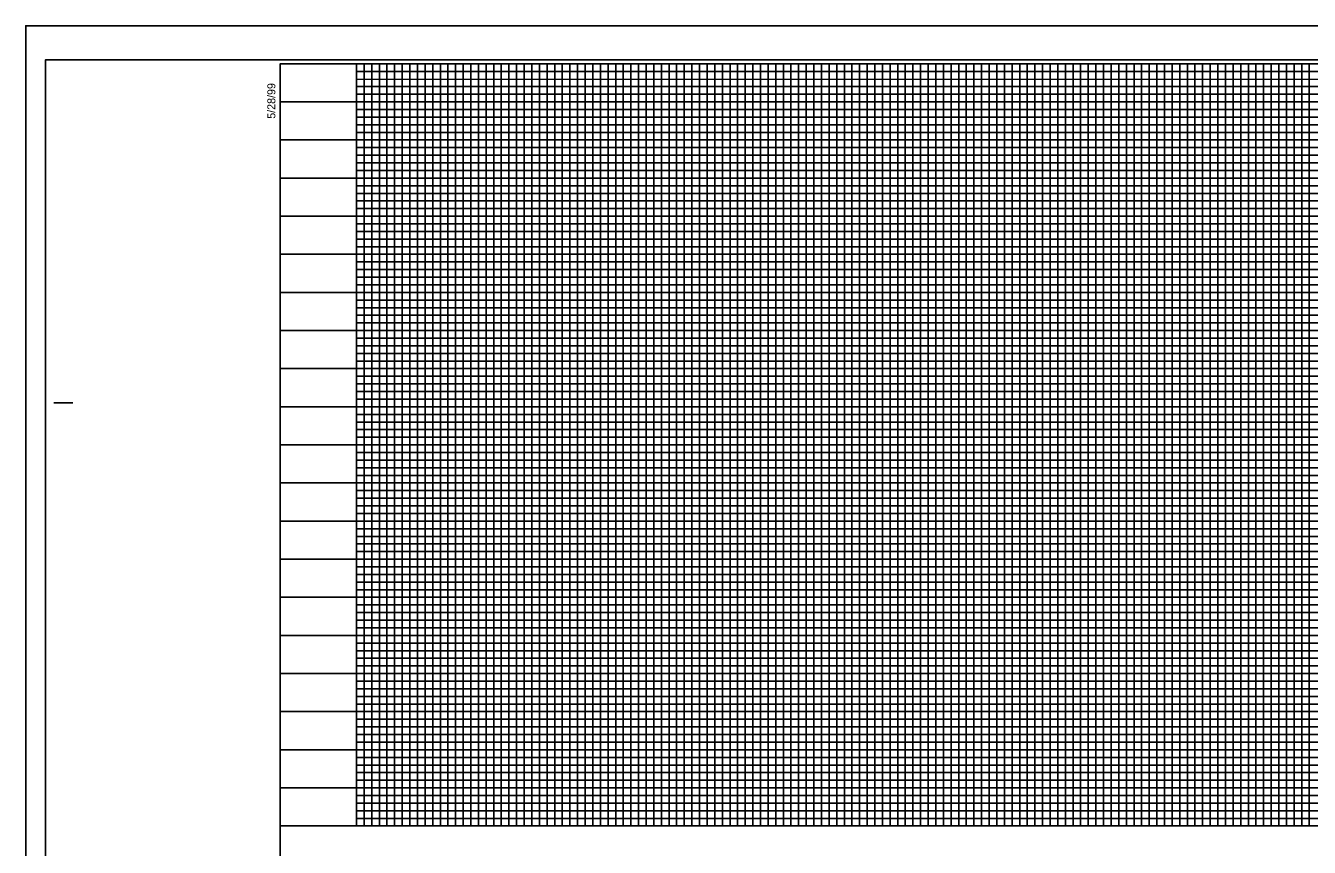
# Model space of a CAD drawing. Extents: x 2331575 to 2333259, y 609001 to 610101.
# Drawn here: x 2331575 to 2332417, y 609562 to 610101 of the extents above; entities that cross this region are included whole.
import ezdxf

# ---------------------------------------------------------------- set-up
doc = ezdxf.new("R2010")
doc.units = 0
for name, color, linetype in [('Sheet Cutting Line CELL', 7, 'Continuous'), ('Sheet DOT Grid CELL', 7, 'Continuous'), ('Sheet Layout Profile Border Port 1', 7, 'Continuous'), ('Sheet Plot Border Inside CELL', 7, 'Continuous'), ('Sheet Plot Border Outside CELL', 7, 'Continuous'), ('Sheet Profile CELL', 7, 'Continuous'), ('Sheet Profile Grid Major CELL', 7, 'Continuous'), ('Sheet Profile Grid Middle CELL', 7, 'Continuous'), ('Sheet Profile Grid Minor CELL', 7, 'Continuous')]:
    doc.layers.add(name, color=color, linetype=linetype)

msp = doc.modelspace()

# ---------------------------------------------------------------- linework, layer by layer
at = {"layer": 'Sheet Cutting Line CELL'}
for p, q in [((2333259.23, 610101.48), (2331575.23, 610101.48)), ((2331575.23, 610101.48), (2331575.23, 609001.48))]:
    msp.add_line(p, q, dxfattribs=at)
at = {"layer": 'Sheet DOT Grid CELL'}
for p, q in [((2331792.23, 609576.48), (2331792.23, 610076.48)), ((2331842.23, 609576.48), (2331842.23, 610076.48)), ((2331892.23, 609576.48), (2331892.23, 610076.48)), ((2331942.23, 609576.48), (2331942.23, 610076.48)), ((2331992.23, 609576.48), (2331992.23, 610076.48)), ((2332042.23, 609576.48), (2332042.23, 610076.48)), ((2332092.23, 609576.48), (2332092.23, 610076.48)), ((2332142.23, 609576.48), (2332142.23, 610076.48)), ((2332192.23, 609576.48), (2332192.23, 610076.48)), ((2332242.23, 609576.48), (2332242.23, 610076.48)), ((2332292.23, 609576.48), (2332292.23, 610076.48)), ((2332342.23, 609576.48), (2332342.23, 610076.48)), ((2332392.23, 609576.48), (2332392.23, 610076.48)), ((2333042.18, 610026.48), (2331742.23, 610026.48)), ((2333042.18, 609976.48), (2331742.23, 609976.48)), ((2333042.23, 609926.48), (2331742.23, 609926.48)), ((2333242.23, 609876.48), (2331742.23, 609876.48)), ((2333242.23, 609826.48), (2331742.23, 609826.48)), ((2333242.23, 609776.48), (2331742.23, 609776.48)), ((2333242.23, 609726.48), (2331742.23, 609726.48)), ((2333242.23, 609676.48), (2331742.23, 609676.48)), ((2333242.23, 609626.48), (2331742.23, 609626.48))]:
    msp.add_line(p, q, dxfattribs=at)
at = {"layer": 'Sheet Layout Profile Border Port 1'}
msp.add_lwpolyline([(2331792.23, 609915.43), (2331792.23, 609576.48), (2333192.23, 609576.48), (2333192.23, 609915.43)], dxfattribs=at)
at = {"layer": 'Sheet Plot Border Inside CELL'}
msp.add_lwpolyline([(2331588.23, 609023.93), (2333254.73, 609023.93), (2333254.73, 610079.03), (2331588.23, 610079.03)], close=True, dxfattribs=at)
at = {"layer": 'Sheet Plot Border Outside CELL'}
msp.add_lwpolyline([(2331575.23, 609001.48), (2333259.23, 609001.48), (2333259.23, 610101.48), (2331575.23, 610101.48)], close=True, dxfattribs=at)
at = {"layer": 'Sheet Profile CELL'}
for p, q in [((2331593.73, 609853.98), (2331606.23, 609853.98)), ((2331742.23, 609576.48), (2333242.23, 609576.48))]:
    msp.add_line(p, q, dxfattribs=at)
msp.add_lwpolyline([(2333242.23, 610076.48), (2331742.23, 610076.48), (2331742.23, 609026.48), (2333242.23, 609026.48)], close=True, dxfattribs=at)
at = {"layer": 'Sheet Profile Grid Major CELL'}
for points in [[(2331792.23, 610076.48), (2331792.23, 609576.48), (2331842.23, 609576.48), (2331842.23, 610076.48), (2331892.23, 610076.48), (2331892.23, 609576.48), (2331942.23, 609576.48), (2331942.23, 610076.48), (2331992.23, 610076.48), (2331992.23, 609576.48), (2332042.23, 609576.48), (2332042.23, 610076.48), (2332092.23, 610076.48), (2332092.23, 609576.48), (2332142.23, 609576.48), (2332142.23, 610076.48), (2332192.23, 610076.48), (2332192.23, 609576.48), (2332242.23, 609576.48), (2332242.23, 610076.48), (2332292.23, 610076.48), (2332292.23, 609576.48), (2332342.23, 609576.48), (2332342.23, 610076.48), (2332392.23, 610076.48), (2332392.23, 609576.48), (2332442.23, 609576.48)], [(2331742.23, 610026.48), (2333042.23, 610026.48)], [(2333042.23, 609976.48), (2331742.23, 609976.48), (2331742.23, 609926.48), (2333042.23, 609926.48)], [(2333242.23, 609876.48), (2331742.23, 609876.48), (2331742.23, 609826.48), (2333242.23, 609826.48)], [(2333242.23, 609776.48), (2331742.23, 609776.48), (2331742.23, 609726.48), (2333242.23, 609726.48)], [(2333242.23, 609676.48), (2331742.23, 609676.48), (2331742.23, 609676.48), (2331742.23, 609626.48), (2333242.23, 609626.48)]]:
    msp.add_lwpolyline(points, dxfattribs=at)
at = {"layer": 'Sheet Profile Grid Middle CELL'}
msp.add_line((2331742.23, 610051.48), (2333042.18, 610051.48), dxfattribs=at)
for points in [[(2331817.23, 610076.48), (2331817.23, 609576.48), (2331867.23, 609576.48), (2331867.23, 610076.48), (2331917.23, 610076.48), (2331917.23, 609576.48), (2331967.23, 609576.48), (2331967.23, 610076.48), (2332017.23, 610076.48), (2332017.23, 609576.48), (2332067.23, 609576.48), (2332067.23, 610076.48), (2332117.23, 610076.48), (2332117.23, 609576.48), (2332167.23, 609576.48), (2332167.23, 610076.48), (2332217.23, 610076.48), (2332217.23, 609576.48), (2332267.23, 609576.48), (2332267.23, 610076.48), (2332317.23, 610076.48), (2332317.23, 609576.48), (2332367.23, 609576.48), (2332367.23, 609576.48), (2332367.23, 610076.48), (2332417.23, 610076.48), (2332417.23, 609576.48), (2332467.23, 609576.48)], [(2333042.23, 610001.48), (2331742.23, 610001.48), (2331742.23, 609951.48), (2333042.23, 609951.48)], [(2333242.23, 609901.48), (2331742.23, 609901.48), (2331742.23, 609851.48), (2333067.23, 609851.48)], [(2333242.23, 609801.48), (2331742.23, 609801.48), (2331742.23, 609751.48), (2333242.23, 609751.48)], [(2333242.23, 609701.48), (2331742.23, 609701.48), (2331742.23, 609651.48), (2333242.23, 609651.48)], [(2333242.23, 609601.48), (2331742.23, 609601.48)]]:
    msp.add_lwpolyline(points, dxfattribs=at)
at = {"layer": 'Sheet Profile Grid Minor CELL'}
for p, q in [((2331792.23, 610071.48), (2333042.23, 610071.48)), ((2331792.23, 610066.48), (2331792.23, 610066.48)), ((2333042.23, 610066.48), (2331792.23, 610066.13)), ((2331792.23, 610061.48), (2333042.23, 610061.48)), ((2333042.18, 609941.48), (2331792.23, 609941.48)), ((2333042.23, 609936.48), (2331792.23, 609936.48)), ((2333042.23, 609931.48), (2331792.23, 609931.48)), ((2331792.23, 609921.48), (2333042.23, 609921.48)), ((2333042.23, 609916.48), (2331792.23, 609916.48)), ((2331792.23, 609911.48), (2333192.23, 609911.48)), ((2333192.23, 609891.48), (2331792.23, 609891.48)), ((2331792.23, 609886.48), (2333192.23, 609886.48)), ((2333192.23, 609866.48), (2331792.23, 609866.48)), ((2331792.23, 609861.48), (2333192.23, 609861.48)), ((2333192.23, 609841.48), (2331792.23, 609841.48)), ((2331792.23, 609836.48), (2333192.23, 609836.48)), ((2333192.23, 609831.48), (2331792.23, 609831.48)), ((2331792.23, 609821.48), (2333192.23, 609821.48)), ((2333192.23, 609816.48), (2331792.23, 609816.48)), ((2331792.23, 609811.48), (2333192.23, 609811.48)), ((2333192.23, 609806.48), (2331792.23, 609806.48)), ((2331792.23, 609796.48), (2333192.23, 609796.48)), ((2333192.23, 609791.48), (2331792.23, 609791.48)), ((2331792.23, 609786.48), (2333192.23, 609786.48)), ((2333192.23, 609781.48), (2331792.23, 609781.48)), ((2331792.23, 609771.48), (2333192.23, 609771.48)), ((2333192.23, 609766.48), (2331792.23, 609766.48)), ((2331792.23, 609761.48), (2333192.23, 609761.48)), ((2333192.23, 609756.48), (2331792.23, 609756.48)), ((2331792.23, 609746.48), (2333192.23, 609746.48)), ((2333192.23, 609741.48), (2331792.23, 609741.48)), ((2331792.23, 609736.48), (2333192.23, 609736.48)), ((2333192.23, 609731.48), (2331792.23, 609731.48)), ((2331792.23, 609721.48), (2333192.23, 609721.48)), ((2333192.23, 609716.48), (2331792.23, 609716.48)), ((2331792.23, 609711.48), (2333192.23, 609711.48)), ((2333192.23, 609706.48), (2331792.23, 609706.48)), ((2331792.23, 609696.48), (2333192.23, 609696.48)), ((2333192.23, 609691.48), (2331792.23, 609691.48)), ((2333192.23, 609686.48), (2331792.23, 609686.48)), ((2333192.23, 609681.48), (2331792.23, 609681.48)), ((2331792.23, 609671.48), (2333192.23, 609671.48)), ((2333192.23, 609666.48), (2331792.23, 609666.48)), ((2331792.23, 609661.48), (2333192.23, 609661.48)), ((2333192.23, 609656.48), (2331792.23, 609656.48)), ((2331792.23, 609646.48), (2333192.23, 609646.48)), ((2333192.23, 609641.48), (2331792.23, 609641.48)), ((2331792.23, 609636.48), (2333192.23, 609636.48)), ((2333192.23, 609631.48), (2331792.23, 609631.48)), ((2331792.23, 609621.48), (2333192.23, 609621.48)), ((2333192.23, 609616.48), (2331792.23, 609616.48)), ((2331792.23, 609611.48), (2333192.23, 609611.48)), ((2333192.23, 609606.48), (2331792.23, 609606.48)), ((2331792.23, 609596.48), (2333192.23, 609596.48)), ((2333192.23, 609591.48), (2331792.23, 609591.48)), ((2331792.23, 609586.48), (2333192.23, 609586.48))]:
    msp.add_line(p, q, dxfattribs=at)
for points in [[(2331797.23, 610076.48), (2331797.23, 609576.48), (2331802.23, 609576.48), (2331802.23, 610076.48), (2331807.23, 610076.48), (2331807.23, 609576.48), (2331812.23, 609576.48), (2331812.23, 610076.48), (2331822.23, 610076.48), (2331822.23, 609576.48), (2331827.23, 609576.48), (2331827.23, 610076.48), (2331832.23, 610076.48), (2331832.23, 609576.48), (2331837.23, 609576.48), (2331847.23, 609576.48), (2331852.23, 609576.48), (2331852.23, 610076.48), (2331857.23, 610076.48), (2331857.23, 609576.48), (2331862.23, 609576.48), (2331862.23, 610076.48), (2331872.23, 610076.48), (2331872.23, 609576.48), (2331877.23, 609576.48), (2331877.23, 610076.48), (2331882.23, 610076.48), (2331882.23, 609576.48), (2331887.23, 609576.48), (2331887.23, 610076.48), (2331897.23, 610076.48), (2331897.23, 609576.48), (2331902.23, 609576.48), (2331902.23, 610076.48), (2331907.23, 610076.48), (2331907.23, 609576.48), (2331912.23, 609576.48), (2331912.23, 610076.48), (2331922.23, 610076.48), (2331922.23, 609576.48), (2331927.23, 609576.48), (2331927.23, 610076.48), (2331932.23, 610076.48), (2331932.23, 609576.48), (2331937.23, 609576.48), (2331937.23, 610076.48), (2331947.23, 610076.48), (2331947.23, 609576.48), (2331952.23, 609576.48), (2331952.23, 610076.48), (2331957.23, 610076.48), (2331957.23, 609576.48), (2331962.23, 609576.48), (2331962.23, 610076.48), (2331972.23, 610076.48), (2331972.23, 609576.48), (2331977.23, 609576.48), (2331977.23, 610076.48), (2331982.23, 610076.48), (2331982.23, 609576.48), (2331987.23, 609576.48), (2331987.23, 610076.48), (2331997.23, 610076.48), (2331997.23, 609576.48), (2332002.23, 609576.48), (2332002.23, 610076.48), (2332007.23, 610076.48), (2332007.23, 609576.48)], [(2331837.23, 609576.48), (2331837.23, 610076.48), (2331847.23, 610076.48), (2331847.23, 609576.48)], [(2332007.23, 609576.48), (2332012.23, 609576.48), (2332012.23, 610076.48), (2332022.23, 610076.48), (2332022.23, 609576.48), (2332027.23, 609576.48), (2332027.23, 610076.48), (2332032.23, 610076.48), (2332032.23, 609576.48), (2332037.23, 609576.48), (2332037.23, 610076.48), (2332047.23, 610076.48), (2332047.23, 609576.48), (2332052.23, 609576.48), (2332052.23, 610076.48), (2332057.23, 610076.48), (2332057.23, 609576.48), (2332062.23, 609576.48), (2332062.23, 610076.48), (2332072.23, 610076.48), (2332072.23, 609576.48), (2332077.23, 609576.48), (2332077.23, 610076.48), (2332082.23, 610076.48), (2332082.23, 609576.48), (2332087.23, 609576.48), (2332087.23, 610076.48), (2332097.23, 610076.48), (2332097.23, 609576.48), (2332102.23, 609576.48), (2332102.23, 610076.48), (2332107.23, 610076.48), (2332107.23, 609576.48), (2332112.23, 609576.48), (2332112.23, 610076.48), (2332122.23, 610076.48), (2332122.23, 609576.48), (2332127.23, 609576.48), (2332127.23, 610076.48), (2332132.23, 610076.48), (2332132.23, 609576.48), (2332137.23, 609576.48), (2332137.23, 610076.48), (2332147.23, 610076.48), (2332147.23, 609576.48), (2332152.23, 609576.48), (2332152.23, 610076.48), (2332157.23, 610076.48), (2332157.23, 609576.48), (2332162.23, 609576.48), (2332162.23, 610076.48), (2332172.23, 610076.48), (2332172.23, 609576.48), (2332177.23, 609576.48), (2332177.23, 610076.48), (2332182.23, 610076.48), (2332182.23, 609576.48), (2332187.23, 609576.48), (2332187.23, 610076.48), (2332197.23, 610076.48), (2332197.23, 609576.48), (2332202.23, 609576.48), (2332202.23, 610076.48), (2332207.23, 610076.48), (2332207.23, 609576.48), (2332212.23, 609576.48), (2332212.23, 610076.48), (2332222.23, 610076.48), (2332222.23, 609576.48), (2332227.23, 609576.48), (2332227.23, 610076.48), (2332232.23, 610076.48), (2332232.23, 609576.48), (2332237.23, 609576.48), (2332237.23, 610076.48), (2332247.23, 610076.48), (2332247.23, 609576.48), (2332252.23, 609576.48), (2332252.23, 610076.48), (2332257.23, 610076.48), (2332257.23, 609576.48), (2332262.23, 609576.48), (2332262.23, 610076.48), (2332272.23, 610076.48), (2332272.23, 609576.48), (2332277.23, 609576.48), (2332277.23, 610076.48), (2332282.23, 610076.48), (2332282.23, 609576.48), (2332287.23, 609576.48), (2332287.23, 610076.48), (2332297.23, 610076.48), (2332297.23, 609576.48), (2332302.23, 609576.48), (2332302.23, 610076.48), (2332307.23, 610076.48), (2332307.23, 609576.48), (2332312.23, 609576.48), (2332312.23, 610076.48), (2332322.23, 610076.48)], [(2332322.23, 610076.48), (2332322.23, 609576.48), (2332327.23, 609576.48), (2332327.23, 610076.48), (2332332.23, 610076.48), (2332332.23, 609576.48), (2332337.23, 609576.48), (2332337.23, 610076.48), (2332347.23, 610076.48), (2332347.23, 609576.48), (2332352.23, 609576.48), (2332352.23, 610076.48), (2332357.23, 610076.48), (2332357.23, 609576.48), (2332362.23, 609576.48), (2332362.23, 610076.48), (2332372.23, 610076.48), (2332372.23, 609576.48), (2332377.23, 609576.48), (2332377.23, 610076.48), (2332382.23, 610076.48), (2332382.23, 609576.48), (2332387.23, 609576.48), (2332387.23, 610076.48), (2332397.23, 610076.48), (2332397.23, 609576.48), (2332402.23, 609576.48), (2332402.23, 610076.48), (2332407.23, 610076.48), (2332407.23, 609576.48), (2332412.23, 609576.48), (2332412.23, 610076.48), (2332422.23, 610076.48)], [(2333042.23, 610056.48), (2331792.23, 610056.48), (2331792.23, 610046.48), (2333042.23, 610046.48)], [(2333042.18, 610041.48), (2331792.23, 610041.48), (2331792.23, 610036.48), (2333042.23, 610036.48)], [(2333042.23, 610031.48), (2331792.23, 610031.48), (2331792.23, 610021.48), (2333042.23, 610021.48)], [(2333042.23, 610016.48), (2331792.23, 610016.48), (2331792.23, 610011.48), (2333042.23, 610011.48)], [(2333042.23, 610006.48), (2331792.23, 610006.48), (2331792.23, 609996.48), (2333042.23, 609996.48)], [(2333042.23, 609991.48), (2331792.23, 609991.48), (2331792.23, 609986.48), (2333042.23, 609986.48)], [(2333042.23, 609981.48), (2331792.23, 609981.48), (2331792.23, 609971.48), (2333042.23, 609971.48)], [(2333042.23, 609966.38), (2331792.33, 609966.38), (2331792.33, 609961.48), (2333042.23, 609961.48)], [(2333042.23, 609956.48), (2331792.23, 609956.48), (2331792.23, 609946.48), (2333042.23, 609946.48)], [(2333192.23, 609906.48), (2331792.23, 609906.48), (2331792.23, 609896.48), (2333192.23, 609896.48)], [(2333192.23, 609881.48), (2331792.23, 609881.48), (2331792.23, 609871.48), (2333192.23, 609871.48)], [(2333192.23, 609856.48), (2331792.23, 609856.48), (2331792.23, 609846.48), (2333192.23, 609846.48)], [(2333192.23, 609581.48), (2331792.23, 609581.48)]]:
    msp.add_lwpolyline(points, dxfattribs=at)

# ---------------------------------------------------------------- texts
at = {"layer": 'Sheet Profile CELL'}
msp.add_text('5/28/99', height=5.25, rotation=90, dxfattribs=at).set_placement((2331738.99, 610040.39))

doc.saveas('drawing.dxf')
